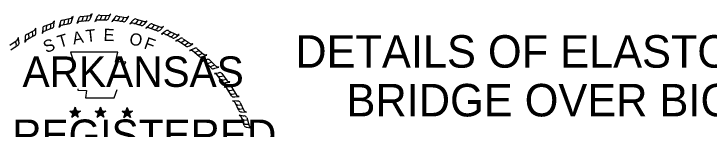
# Model space of a CAD drawing. Extents: x -193 to 149, y 507 to 725.
# Drawn here: x 58.22 to 101.13, y 533.07 to 540.16 of the extents above; entities that cross this region are included whole.
import ezdxf

# ---------------------------------------------------------------- set-up
doc = ezdxf.new("R2010")
doc.units = 0
doc.layers.add('Border 2660-Hwy18 - Stamp-ChrisC', color=7, linetype='Continuous')
doc.layers.add('Title Text', color=7, linetype='Continuous')

msp = doc.modelspace()

# ---------------------------------------------------------------- linework, layer by layer
at = {"layer": 'Border 2660-Hwy18 - Stamp-ChrisC'}
for p, q in [((61.207, 539.768), (61.74, 539.888)), ((61.597, 539.633), (61.612, 539.85)), ((61.8, 539.745), (61.875, 540)), ((61.875, 540), (61.845, 539.978)), ((62.22, 539.835), (62.107, 539.58)), ((62.22, 539.835), (62.212, 539.813)), ((62.235, 539.895), (62.22, 539.835)), ((62.37, 540), (62.91, 540.053)), ((62.467, 539.798), (62.52, 540.015)), ((62.73, 539.828), (62.782, 540.038)), ((62.932, 539.858), (62.955, 539.903)), ((62.955, 539.903), (63.045, 540.158)), ((63.045, 540.158), (63.015, 540.135)), ((63.345, 539.933), (63.21, 539.693)), ((63.345, 539.933), (63.337, 539.91)), ((63.367, 539.993), (63.345, 539.933)), ((63.517, 540.083), (64.057, 540.068)), ((63.585, 539.873), (63.667, 540.075)), ((63.855, 539.865), (63.93, 540.075)), ((64.057, 539.873), (64.08, 539.918)), ((64.08, 539.918), (64.207, 540.158)), ((64.207, 540.158), (64.177, 540.143)), ((64.44, 539.903), (64.275, 539.693)), ((64.44, 539.903), (64.432, 539.888)), ((64.47, 539.963), (64.44, 539.903)), ((64.627, 540.03), (65.16, 539.948)), ((64.672, 539.813), (64.777, 540.008)), ((64.935, 539.768), (65.032, 539.963)), ((65.167, 539.79), (65.325, 540.015)), ((65.325, 540.015), (65.295, 540)), ((65.767, 539.835), (66.292, 539.693)), ((60.097, 539.408), (60.615, 539.595)), ((60.24, 539.25), (60.255, 539.46)), ((60.502, 539.34), (60.495, 539.55)), ((60.69, 539.468), (60.727, 539.738)), ((60.69, 539.415), (60.69, 539.468)), ((60.727, 539.738), (60.705, 539.708)), ((61.08, 539.595), (60.997, 539.333)), ((61.08, 539.655), (61.08, 539.595)), ((61.08, 539.595), (61.08, 539.565)), ((61.68, 539.558), (61.14, 539.453)), ((61.327, 539.58), (61.357, 539.805)), ((61.785, 539.693), (61.8, 539.745)), ((62.107, 539.58), (62.152, 539.618)), ((62.805, 539.738), (62.265, 539.685)), ((63.21, 539.693), (63.255, 539.723)), ((63.93, 539.775), (63.382, 539.783)), ((64.275, 539.693), (64.32, 539.715)), ((64.987, 539.67), (64.447, 539.753)), ((65.137, 539.753), (65.167, 539.79)), ((65.572, 539.745), (65.377, 539.55)), ((65.377, 539.55), (65.43, 539.565)), ((65.572, 539.745), (65.557, 539.73)), ((66.082, 539.438), (65.557, 539.595)), ((65.602, 539.798), (65.572, 539.745)), ((65.782, 539.618), (65.91, 539.798)), ((66.045, 539.543), (66.172, 539.73)), ((66.24, 539.498), (66.277, 539.535)), ((66.277, 539.535), (66.457, 539.73)), ((66.577, 539.46), (66.367, 539.28)), ((66.457, 539.73), (66.427, 539.723)), ((66.577, 539.46), (66.562, 539.445)), ((66.607, 539.505), (66.577, 539.46)), ((66.78, 539.535), (67.29, 539.34)), ((66.78, 539.318), (66.922, 539.483)), ((59.002, 538.883), (59.475, 539.138)), ((59.392, 538.875), (59.37, 539.085)), ((59.572, 539.288), (59.55, 539.265)), ((59.572, 539.025), (59.572, 539.288)), ((59.572, 538.973), (59.572, 539.025)), ((60.007, 539.22), (59.97, 538.958)), ((59.97, 538.958), (60, 538.988)), ((60, 539.273), (60.007, 539.22)), ((60.007, 539.22), (60, 539.19)), ((60.592, 539.288), (60.075, 539.085)), ((60.997, 539.333), (61.035, 539.37)), ((66.367, 539.28), (66.42, 539.295)), ((67.057, 539.108), (66.555, 539.31)), ((67.035, 539.22), (67.17, 539.385)), ((67.23, 539.16), (67.267, 539.19)), ((67.267, 539.19), (67.462, 539.378)), ((67.567, 539.07), (67.335, 538.92)), ((67.462, 539.378), (67.425, 539.37)), ((67.567, 539.07), (67.537, 539.055)), ((67.597, 539.108), (67.567, 539.07)), ((67.747, 538.913), (67.912, 539.048)), ((67.762, 539.123), (68.242, 538.883)), ((57.975, 538.238), (58.425, 538.538)), ((58.507, 538.703), (58.477, 538.68)), ((58.53, 538.44), (58.507, 538.703)), ((58.92, 538.68), (58.905, 538.418)), ((58.912, 538.74), (58.92, 538.68)), ((58.92, 538.68), (58.927, 538.658)), ((59.497, 538.823), (59.017, 538.568)), ((59.16, 538.748), (59.13, 538.958)), ((67.335, 538.92), (67.387, 538.913)), ((68.01, 538.68), (67.515, 538.935)), ((67.987, 538.793), (68.137, 538.935)), ((68.175, 538.703), (68.212, 538.733)), ((68.445, 538.605), (68.197, 538.493)), ((68.212, 538.733), (68.43, 538.883)), ((68.43, 538.883), (68.392, 538.898)), ((68.445, 538.605), (68.422, 538.598)), ((68.482, 538.643), (68.445, 538.605)), ((68.61, 538.433), (68.775, 538.553)), ((68.662, 538.635), (69.105, 538.335)), ((58.485, 538.238), (58.027, 537.923)), ((58.38, 538.275), (58.32, 538.47)), ((58.545, 538.388), (58.53, 538.44)), ((58.905, 538.418), (58.942, 538.448)), ((68.197, 538.493), (68.242, 538.485)), ((68.842, 538.178), (68.385, 538.478)), ((68.835, 538.29), (69, 538.403)), ((69.007, 538.178), (69.052, 538.2)), ((69.052, 538.2), (69.277, 538.32)), ((69.277, 538.32), (69.247, 538.343)), ((69.322, 538.005), (69.067, 537.915)), ((69.067, 537.915), (69.112, 537.9)), ((69.667, 537.533), (69.24, 537.885)), ((69.322, 538.005), (69.3, 537.998)), ((69.36, 538.043), (69.322, 538.005)), ((69.465, 537.818), (69.652, 537.915)), ((69.532, 538.02), (69.945, 537.668)), ((69.675, 537.645), (69.855, 537.75)), ((69.832, 537.518), (69.877, 537.54)), ((70.11, 537.33), (69.855, 537.263)), ((69.855, 537.263), (69.9, 537.233)), ((69.877, 537.54), (70.125, 537.63)), ((70.11, 537.33), (70.087, 537.315)), ((70.125, 537.63), (70.095, 537.653)), ((70.155, 537.353), (70.11, 537.33)), ((70.32, 537.315), (70.695, 536.933)), ((70.41, 536.82), (70.02, 537.218)), ((70.245, 537.128), (70.432, 537.203)), ((70.425, 536.933), (70.62, 537.023)), ((70.62, 536.813), (70.882, 536.888)), ((70.882, 536.888), (70.852, 536.903)), ((70.575, 536.79), (70.62, 536.813)), ((70.86, 536.52), (70.597, 536.49)), ((70.597, 536.49), (70.635, 536.46)), ((71.085, 535.973), (70.755, 536.423)), ((70.86, 536.52), (70.837, 536.513)), ((70.905, 536.543), (70.86, 536.52)), ((71.062, 536.483), (71.385, 536.048)), ((70.957, 536.303), (71.16, 536.348)), ((71.115, 536.085), (71.317, 536.145)), ((71.295, 535.935), (71.557, 535.965)), ((71.557, 535.965), (71.527, 535.995)), ((71.475, 535.673), (71.205, 535.673)), ((71.205, 535.673), (71.242, 535.635)), ((71.242, 535.92), (71.295, 535.935)), ((71.647, 535.118), (71.362, 535.59)), ((71.475, 535.673), (71.445, 535.68)), ((71.52, 535.695), (71.475, 535.673)), ((71.67, 535.62), (71.955, 535.163)), ((71.55, 535.448), (71.76, 535.485)), ((71.692, 535.223), (71.895, 535.268)), ((72, 534.788), (71.722, 534.81)), ((71.722, 534.81), (71.767, 534.78)), ((71.805, 535.05), (71.85, 535.058)), ((71.85, 535.058), (72.12, 535.065)), ((72.097, 534.203), (71.872, 534.713)), ((72, 534.788), (71.97, 534.788)), ((72.06, 534.803), (72, 534.788)), ((72.12, 535.065), (72.09, 535.095)), ((72.195, 534.713), (72.42, 534.218)), ((62.002, 534.413), (61.95, 534.188)), ((62.002, 534.413), (61.965, 534.18)), ((62.002, 534.413), (61.987, 534.18)), ((62.002, 534.075), (62.002, 534.413)), ((62.002, 534.413), (62.062, 534.18)), ((62.002, 534.413), (62.047, 534.18)), ((62.002, 534.413), (62.025, 534.18)), ((63.57, 534.413), (63.51, 534.188)), ((63.57, 534.413), (63.532, 534.18)), ((63.57, 534.413), (63.547, 534.18)), ((63.57, 534.075), (63.57, 534.413)), ((63.57, 534.413), (63.63, 534.18)), ((63.57, 534.413), (63.615, 534.18)), ((63.57, 534.413), (63.585, 534.18)), ((65.22, 534.405), (65.167, 534.173)), ((65.22, 534.405), (65.182, 534.173)), ((65.22, 534.405), (65.205, 534.173)), ((65.22, 534.06), (65.22, 534.405)), ((65.22, 534.405), (65.287, 534.173)), ((65.22, 534.405), (65.272, 534.173)), ((65.22, 534.405), (65.242, 534.173)), ((72.045, 534.548), (72.27, 534.563)), ((72.157, 534.3), (72.375, 534.33)), ((61.672, 534.18), (62.002, 534.075)), ((61.672, 534.18), (61.912, 534.15)), ((61.672, 534.18), (61.912, 534.135)), ((61.672, 534.18), (61.905, 534.12)), ((61.672, 534.18), (61.897, 534.083)), ((61.672, 534.18), (61.897, 534.06)), ((61.672, 534.18), (61.897, 534.038)), ((61.8, 533.798), (62.002, 534.075)), ((61.8, 533.798), (61.905, 534.053)), ((61.8, 533.798), (61.92, 534.023)), ((61.8, 533.798), (61.935, 534.015)), ((61.8, 533.798), (62.002, 534)), ((61.8, 533.798), (61.965, 533.993)), ((61.8, 533.798), (62.002, 533.97)), ((62.325, 534.18), (62.002, 534.075)), ((62.197, 533.798), (62.002, 534.075)), ((62.197, 533.798), (62.002, 533.993)), ((62.197, 533.798), (62.002, 533.97)), ((62.197, 533.798), (62.032, 533.993)), ((62.325, 534.18), (62.04, 534.158)), ((62.325, 534.18), (62.062, 534.128)), ((62.325, 534.18), (62.062, 534.113)), ((62.197, 533.798), (62.062, 534.023)), ((62.197, 533.798), (62.07, 534.068)), ((62.197, 533.798), (62.092, 534.068)), ((62.325, 534.18), (62.122, 534.09)), ((62.325, 534.18), (62.137, 534.083)), ((62.325, 534.18), (62.152, 534.068)), ((63.24, 534.18), (63.57, 534.075)), ((63.24, 534.18), (63.48, 534.15)), ((63.24, 534.18), (63.472, 534.135)), ((63.24, 534.18), (63.472, 534.12)), ((63.24, 534.18), (63.465, 534.083)), ((63.24, 534.18), (63.457, 534.06)), ((63.24, 534.18), (63.457, 534.038)), ((63.367, 533.798), (63.57, 534.075)), ((63.367, 533.798), (63.472, 534.053)), ((63.367, 533.798), (63.48, 534.023)), ((63.367, 533.798), (63.502, 534.015)), ((63.367, 533.798), (63.562, 534)), ((63.367, 533.798), (63.532, 533.993)), ((63.367, 533.798), (63.57, 533.97)), ((63.765, 533.798), (63.562, 533.993)), ((63.765, 533.798), (63.562, 533.97)), ((63.892, 534.18), (63.57, 534.075)), ((63.765, 533.798), (63.57, 534.075)), ((63.765, 533.798), (63.6, 533.993)), ((63.892, 534.18), (63.607, 534.158)), ((63.892, 534.18), (63.622, 534.128)), ((63.892, 534.18), (63.622, 534.113)), ((63.765, 533.798), (63.63, 534.023)), ((63.765, 533.798), (63.637, 534.068)), ((63.765, 533.798), (63.66, 534.068)), ((63.892, 534.18), (63.682, 534.09)), ((63.892, 534.18), (63.697, 534.083)), ((63.892, 534.18), (63.712, 534.068)), ((64.897, 534.165), (65.22, 534.06)), ((64.897, 534.165), (65.137, 534.143)), ((64.897, 534.165), (65.137, 534.128)), ((64.897, 534.165), (65.122, 534.105)), ((64.897, 534.165), (65.122, 534.075)), ((64.897, 534.165), (65.115, 534.053)), ((64.897, 534.165), (65.115, 534.03)), ((65.017, 533.783), (65.22, 534.06)), ((65.017, 533.783), (65.122, 534.038)), ((65.017, 533.783), (65.137, 534.015)), ((65.017, 533.783), (65.16, 534.008)), ((65.017, 533.783), (65.22, 533.985)), ((65.017, 533.783), (65.182, 533.978)), ((65.017, 533.783), (65.227, 533.963)), ((65.55, 534.165), (65.22, 534.06)), ((65.422, 533.783), (65.22, 534.06)), ((65.422, 533.783), (65.22, 533.985)), ((65.422, 533.783), (65.22, 533.955)), ((65.55, 534.165), (65.257, 534.143)), ((65.422, 533.783), (65.257, 533.978)), ((65.55, 534.165), (65.28, 534.12)), ((65.55, 534.165), (65.28, 534.105)), ((65.422, 533.783), (65.287, 534.015)), ((65.422, 533.783), (65.295, 534.053)), ((65.422, 533.783), (65.317, 534.06)), ((65.55, 534.165), (65.34, 534.083)), ((65.55, 534.165), (65.355, 534.068)), ((65.55, 534.165), (65.37, 534.06)), ((72.397, 533.873), (72.127, 533.933)), ((72.127, 533.933), (72.172, 533.895)), ((72.255, 534.128), (72.3, 534.128)), ((72.427, 533.288), (72.262, 533.813)), ((72.3, 534.128), (72.577, 534.105)), ((72.397, 533.873), (72.375, 533.88)), ((72.457, 533.888), (72.397, 533.873)), ((72.577, 534.105), (72.547, 534.135)), ((72.412, 533.633), (72.637, 533.618)), ((72.592, 533.775), (72.75, 533.265)), ((72.495, 533.378), (72.712, 533.378)), ((72.57, 533.19), (72.622, 533.183)), ((72.622, 533.183), (72.885, 533.13)), ((72.885, 533.13), (72.862, 533.16))]:
    msp.add_line(p, q, dxfattribs=at)
for points in [[(61.71, 537.81), (61.965, 537.038)], [(65.002, 536.948), (65.137, 537.218), (64.492, 537.195), (64.635, 537.81), (61.71, 537.81)], [(62.175, 535.538), (62.175, 535.463), (62.7, 535.44), (62.647, 534.998), (64.402, 534.998), (64.59, 535.5)], [(62.002, 534.413), (62.197, 533.798), (61.672, 534.18), (62.325, 534.18), (61.8, 533.798), (62.002, 534.413)], [(63.57, 534.413), (63.765, 533.798), (63.24, 534.18), (63.892, 534.18), (63.367, 533.798), (63.57, 534.413)], [(65.22, 534.405), (65.422, 533.783), (64.897, 534.165), (65.55, 534.165), (65.017, 533.783), (65.22, 534.405)]]:
    msp.add_lwpolyline(points, dxfattribs=at)
for centre, radius in [((61.998, 534.076), 0.161), ((61.998, 534.076), 0.146), ((61.998, 534.076), 0.136), ((61.998, 534.076), 0.124), ((61.998, 534.076), 0.109), ((61.998, 534.076), 0.101), ((61.998, 534.076), 0.0929), ((61.998, 534.076), 0.08), ((61.998, 534.076), 0.0701), ((61.998, 534.076), 0.0583), ((61.998, 534.076), 0.0464), ((61.998, 534.076), 0.0346), ((61.998, 534.076), 0.0278), ((61.998, 534.076), 0.0135), ((63.563, 534.076), 0.161), ((63.563, 534.076), 0.146), ((63.563, 534.076), 0.136), ((63.563, 534.076), 0.124), ((63.563, 534.076), 0.109), ((63.563, 534.076), 0.101), ((63.563, 534.076), 0.0929), ((63.563, 534.076), 0.08), ((63.563, 534.076), 0.0701), ((63.563, 534.076), 0.0583), ((63.563, 534.076), 0.0464), ((63.563, 534.076), 0.0346), ((63.563, 534.076), 0.0278), ((63.563, 534.076), 0.0135), ((65.219, 534.065), 0.161), ((65.219, 534.065), 0.146), ((65.219, 534.065), 0.136), ((65.219, 534.065), 0.124), ((65.219, 534.065), 0.109), ((65.219, 534.065), 0.101), ((65.219, 534.065), 0.0929), ((65.219, 534.065), 0.08), ((65.219, 534.065), 0.0701), ((65.219, 534.065), 0.0583), ((65.219, 534.065), 0.0464), ((65.219, 534.065), 0.0346), ((65.219, 534.065), 0.0278), ((65.219, 534.065), 0.0135)]:
    msp.add_circle(centre, radius, dxfattribs=at)
for centre, start, end in [((61.696, 540.021), 286.2701, 345.0579), ((62.378, 539.851), 95.6641, 164.0381), ((62.583, 539.879), 275.6641, 344.0381), ((62.787, 539.9), 275.6641, 344.0381), ((62.879, 540.196), 279.9249, 338.7128), ((63.508, 539.931), 89.1628, 157.5368), ((63.451, 539.94), 269.1628, 337.5368), ((63.716, 539.935), 269.1628, 337.5368), ((63.921, 539.933), 269.1628, 337.5368), ((64.045, 540.216), 273.4236, 332.2115), ((64.599, 539.882), 81.4231, 149.797), ((64.543, 539.899), 261.4231, 329.797), ((65.169, 540.092), 265.6839, 324.4717), ((65.721, 539.699), 73.9909, 142.3649), ((60.153, 539.272), 110.5763, 178.9503), ((60.537, 539.424), 290.5763, 358.9503), ((60.549, 539.733), 294.8371, 353.6249), ((61.178, 539.32), 106.2701, 165.0579), ((61.236, 539.624), 102.0093, 170.3833), ((61.178, 539.62), 282.0093, 350.3833), ((61.437, 539.674), 282.0093, 350.3833), ((61.638, 539.717), 282.0093, 350.3833), ((62.286, 539.556), 99.9249, 158.7128), ((62.32, 539.854), 275.6641, 344.0381), ((63.384, 539.648), 93.4236, 152.2115), ((64.437, 539.618), 85.6839, 144.4717), ((64.805, 539.858), 261.4231, 329.797), ((65.008, 539.828), 261.4231, 329.797), ((65.527, 539.458), 78.2517, 137.0395), ((65.669, 539.722), 253.9909, 322.3649), ((65.923, 539.649), 253.9909, 322.3649), ((66.12, 539.593), 253.9909, 322.3649), ((66.314, 539.833), 258.2517, 317.0395), ((66.723, 539.4), 69.0955, 137.4695), ((59.398, 539.268), 301.9545, 0.7423), ((59.424, 538.96), 297.6937, 6.0677), ((60.141, 538.963), 114.8371, 173.6249), ((60.097, 539.26), 290.5763, 358.9503), ((60.345, 539.352), 290.5763, 358.9503), ((66.509, 539.176), 73.3563, 132.1441), ((66.673, 539.428), 249.0955, 317.4695), ((66.919, 539.333), 249.0955, 317.4695), ((67.111, 539.26), 249.0955, 317.4695), ((67.325, 539.483), 253.3563, 312.1441), ((67.697, 538.998), 63.0708, 131.4448), ((58.331, 538.663), 309.1135, 7.9014), ((59.063, 538.761), 117.6937, 186.0677), ((59.089, 538.453), 121.9545, 180.7423), ((59.008, 538.742), 297.6937, 6.0677), ((59.243, 538.864), 297.6937, 6.0677), ((67.461, 538.798), 67.3316, 126.1194), ((67.65, 539.031), 243.0708, 311.4448), ((67.885, 538.911), 243.0708, 311.4448), ((68.069, 538.818), 243.0708, 311.4448), ((68.305, 539.018), 247.3316, 306.1194), ((68.57, 538.523), 56.1736, 124.5476), ((58.227, 538.243), 304.8528, 13.2267), ((58.395, 538.36), 304.8528, 13.2267), ((68.312, 538.353), 60.4344, 119.2222), ((68.527, 538.562), 236.1736, 304.5476), ((68.746, 538.414), 236.1736, 304.5476), ((68.917, 538.3), 236.1736, 304.5476), ((69.175, 538.47), 240.4344, 299.2222), ((69.161, 537.766), 54.451, 113.2388), ((69.398, 537.951), 230.1902, 298.5642), ((69.436, 537.908), 50.1902, 118.5642), ((69.6, 537.781), 230.1902, 298.5642), ((69.758, 537.65), 230.1902, 298.5642), ((69.93, 537.101), 49.2262, 108.0141), ((70.033, 537.792), 234.451, 293.2388), ((70.216, 537.217), 44.9655, 113.3394), ((70.182, 537.263), 224.9655, 293.3394), ((70.368, 537.076), 224.9655, 293.3394), ((70.514, 536.931), 224.9655, 293.3394), ((70.8, 537.047), 229.2262, 288.0141), ((70.648, 536.321), 40.9505, 99.7383), ((70.948, 536.395), 36.6897, 105.0637), ((70.92, 536.446), 216.6897, 285.0637), ((71.078, 536.234), 216.6897, 285.0637), ((71.201, 536.069), 216.6897, 285.0637), ((71.501, 536.143), 220.9505, 279.7383), ((71.242, 535.499), 36.0034, 94.7913), ((71.548, 535.547), 31.7427, 100.1166), ((71.525, 535.6), 211.7427, 280.1166), ((71.663, 535.374), 211.7427, 280.1166), ((71.772, 535.2), 211.7427, 280.1166), ((72.077, 535.248), 216.0034, 274.7913), ((71.749, 534.637), 29.1451, 87.9329), ((72.057, 534.648), 24.8843, 93.2583), ((72.041, 534.704), 204.8843, 273.2583), ((72.151, 534.463), 204.8843, 273.2583), ((72.238, 534.277), 204.8843, 273.2583), ((72.133, 533.757), 22.0938, 80.8817), ((72.547, 534.288), 209.1451, 267.9329), ((72.441, 533.73), 17.8331, 86.207), ((72.432, 533.787), 197.8331, 266.207), ((72.512, 533.535), 197.8331, 266.207), ((72.575, 533.34), 197.8331, 266.207), ((72.883, 533.313), 202.0938, 260.8817)]:
    msp.add_arc(centre, 0.148, start, end, dxfattribs=at)

# ---------------------------------------------------------------- texts
for s, rotation, p in [('A', 11.2132, (61.907, 538.271)), ('T', 6.0228, (62.695, 538.421)), ('E', 358.0732, (63.745, 538.503)), ('O', 350.4515, (65.312, 538.278)), ('S', 21.594, (60.212, 537.738)), ('T', 16.4036, (61.037, 538.068)), ('F', 340.0707, (66.197, 538.053))]:
    msp.add_text(s, height=0.75, rotation=rotation, dxfattribs=at).set_placement(p)
for s, p in [('ARKANSAS', (58.757, 535.668)), ('REGISTERED', (58.12, 531.783))]:
    msp.add_text(s, height=1.875, dxfattribs=at).set_placement(p)
at = {"layer": 'Title Text'}
for s, p in [('DETAILS OF ELASTOMERIC EXPANSION BEARINGS ', (75.593, 536.85)), ('BRIDGE OVER BIG LAKE FLOODWAY RELIEF', (78.755, 533.85))]:
    msp.add_text(s, height=1.99999, dxfattribs=at).set_placement(p)

doc.saveas('drawing.dxf')
